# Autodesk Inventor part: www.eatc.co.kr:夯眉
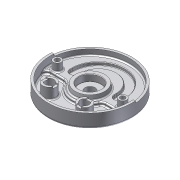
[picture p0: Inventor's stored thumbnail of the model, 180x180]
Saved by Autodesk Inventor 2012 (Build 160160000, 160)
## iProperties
Created: 2015-05
Document SubType Name: Modeling
Density: 2.71 g/cm^3
Material: 알루미늄-6061
Mass: 1082.54 g
Surface Area: 1038.66 cm^2
Volume: 399.463 cm^3
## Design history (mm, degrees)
sketch "스케치1"
  geometry: L1 (-59, -19)-(-59, 19); L2 (59, 19)-(59, -19); L3 (-41, 19)-(-41, -19); L4 (41, -19)-(41, 19); L5 (59, 5)-(41, 5); L6 (-41, 5)-(-59, 5); C1 r 90 at (0, 0); C2 r 95 at (0, 0); A1 r 59 centre (0, 19) between (59, 19) and (-59, 19); A2 r 59 centre (0, -19) between (-59, -19) and (59, -19); A3 r 41 centre (0, -19) between (-41, -19) and (41, -19); A4 r 41 centre (0, 19) between (41, 19) and (-41, 19); 2 further points
  constraints: 12 end point, 8 point on circle, 6 centre point, 5 point on line, 4 tangent, 2 parallel, 1 coincident, 1 collinear, 1 horizontal alignment, 1 midpoint, 1 perpendicular, 1 vertical, 1 vertical alignment, 3 other
  dimensions: "d2" = 180 diameter of C1; "d3" = 156 dimension on A2 A1; "d4" = 118 distance between parallel lines of L2 L1; "d5" = 18 distance between parallel lines of L2 L4; "d8" = 190 diameter of C2; "d117" = 5 distance from line of L5 point (0, 0)
extrude "돌출1" new body sketch "스케치1" distance "d6" = 14; taper "d7" = 0 deg
extrude "돌출2" join sketch "스케치1" distance "d9" = 13; taper "d10" = 0 deg
extrude "돌출3" cut sketch "스케치1" distance "d11" = 7; taper "d12" = 0 deg
sketch "스케치2"
  geometry: C1 r 11.5 at (0, 0); 1 further point
  constraints: 1 centre point, 1 coincident
  dimensions: "d13" = 23 diameter of C1
extrude "돌출4" cut sketch "스케치2" stored distance "d14" = 7; taper "d15" = 0 deg
fillet "모깎기1"
fillet "모깎기2"
sketch "스케치3"
  geometry: L1 (-89.658, 7.844)-(-94.638, 8.28); L2 (89.658, 7.844)-(94.638, 8.28); L3 (0, 0)-(0, -90); A1 r 95 centre (0, 0) between (-94.638, 8.28) and (94.638, 8.28) reference; A2 r 90 centre (0, 0) between (-89.658, 7.844) and (89.658, 7.844) reference; 1 further point
  constraints: 6 end point, 5 point on circle, 1 point on line, 1 vertical, 1 other
  dimensions: "d16" = 190 deg dimension on L2 L1
extrude "돌출5" join sketch "스케치3" distance "d17" = 5; taper "d18" = 0 deg
hole "구멍1" diameter "d21" = 50; stored, may be unused: countersink angle "d25" = 90 deg, drill point angle "d27" = 0 deg; dims "d19" = 10, "d20" = 10, "d22" = 6, "d23" = 4, "d24" = 2, "d26" = 5
fillet "모깎기3" dims "d28" = 0.3
fillet "모깎기5" dims "d42" = 5
sketch "스케치4"
  geometry: C1 r 35 at (0, 0); C2 r 25 at (0, 0); 1 further point
  constraints: 2 centre point, 1 coincident
  dimensions: "d32" = 70 diameter of C1 (derived); "d36" = 10 radial gap between concentric circles of C1 C2
extrude "돌출6" join sketch "스케치4" distance "d33" = 10; taper "d34" = 0 deg
feature "면 기울기2" dims angle "d37" = 10 deg
chamfer "모따기1" distance "d39" = 1; stored, may be unused: second distance "d40" = 2, angle "d41" = 45 deg
sketch "스케치5"
  geometry: L1 (-40.249, -12)-(-89.196, -12); L2 (40.249, -12)-(89.196, -12); A1 r 90 centre (0, 0) between (-89.196, -12) and (89.196, -12) reference; A2 r 42 centre (0, 0) between (-40.249, -12) and (40.249, -12); 1 further point
  constraints: 4 end point, 4 point on circle, 1 centre point, 1 collinear, 1 horizontal, 1 point on line
  dimensions: "d43" = 48 radial gap between concentric circles of A1 A2; "d44" = 12 distance from line of point (0, 0) L1
extrude "돌출7" cut sketch "스케치5" stored distance "d45" = 10; taper "d46" = 0 deg
fillet "모깎기8" dims "d47" = 10
chamfer "모따기2" distance "d49" = 1; stored, may be unused: second distance "d50" = 2, angle "d51" = 45 deg
sketch "스케치7"
  geometry: L1 (36.062, 36.062)-(50.912, 50.912); L2 (-36.062, 36.062)-(-50.912, 50.912); A1 r 72 centre (0, 0) between (50.912, 50.912) and (-50.912, 50.912); A2 r 51 centre (0, 0) between (36.062, 36.062) and (-36.062, 36.062); 1 further point
  constraints: 8 point on circle, 4 end point, 2 centre point, 2 point on line, 1 coincident, 1 horizontal alignment
  dimensions: "d54" = 72 radius of A1; "d55" = 21 radial gap between concentric circles of A1 A2; "d56" = 90 deg angle of L2 L1
extrude "돌출8" join sketch "스케치7" distance "d57" = 5; taper "d58" = 0 deg
fillet "모깎기10" dims "d59" = 5
fillet "모깎기11" dims "d60" = 5
fillet "모깎기12" dims "d61" = 3
sketch "스케치8"
  geometry: C1 r 9 at (74, 0); C2 r 9 at (-74, 0); A1 r 74 centre (0, 0) between (74, 0) and (-74, 0); 1 further point
  constraints: 3 centre point, 2 horizontal alignment, 2 point on circle, 1 coincident, 1 equal radius
  dimensions: "d64" = 18 diameter of C1; "d65" = 148 diameter of A1
extrude "돌출9" join sketch "스케치8" stored distance "d66" = 5; taper "d67" = 0 deg
sketch "스케치11"
  geometry: C1 r 15 at (40, -52); C2 r 15 at (-40, -52); 1 further point
  constraints: 2 centre point, 1 equal radius, 1 horizontal alignment
  dimensions: "d83" = 52 vertical distance of point (0, 0) C1.centre; "d84" = 80 distance of C2.centre C1.centre; "d85" = 40 horizontal distance of point (0, 0) C1.centre (= 0.5 x d84); "d86" = 30 diameter of C1
extrude "돌출10" join sketch "스케치11" stored distance "d87" = 5; taper "d88" = 0 deg
node "구멍3"
node "구멍5"
hole "구멍6" diameter "d93" = 20; stored, may be unused: countersink angle "d97" = 90 deg, drill point angle "d99" = 118 deg; dims "d91" = 10, "d92" = 10, "d94" = 6, "d95" = 4, "d96" = 2, "d98" = 8
hole "구멍7" diameter "d102" = 20; stored, may be unused: countersink angle "d106" = 90 deg, drill point angle "d108" = 118 deg; dims "d100" = 10, "d101" = 10, "d103" = 6, "d104" = 4, "d105" = 2, "d107" = 8
sketch "스케치13"
  geometry: L1 (6, -13.748)-(6, -8); L2 (6, 8)-(6, 13.748); L3 (-6, -13.748)-(-6, -8); L4 (-6, 8)-(-6, 13.748); L5 (-66.252, -6)-(-72, -6); L6 (-88, -6)-(-93.748, -6); L7 (-66.252, 6)-(-72, 6); L8 (-88, 6)-(-93.748, 6); A1 r 15 centre (0, 0) between (6, -13.748) and (6, 13.748) reference; A2 r 10 centre (0, 0) between (6, -8) and (6, 8) reference; A3 r 15 centre (-80, 0) between (-66.252, -6) and (-93.748, -6) reference; A4 r 10 centre (-80, 0) between (-72, -6) and (-88, -6) reference; 1 further point
  constraints: 16 end point, 16 point on circle, 4 equal length, 3 collinear, 2 point on line, 1 perpendicular, 1 vertical
  dimensions: "d109" = 12 distance between parallel lines of L3 L1; "d110" = 6 distance from line of A1.centre L1 (= 0.5 x d109); "d111" = 12 distance between parallel lines of L7 L5; "d112" = 6 distance from line of A3.centre L5 (= 0.5 x d111)
extrude "돌출12" cut sketch "스케치13" distance "d113" = 3; taper "d114" = 0 deg
fillet "모깎기13" dims "d115" = 3
fillet "모깎기14" dims "d116" = 1
sketch "스케치14"
  geometry: C1 r 25 at (0, 0); C2 r 11.5 at (0, 0) reference; 1 further point
  constraints: 1 centre point, 1 coincident
  dimensions: "d120" = 50 diameter of C1
extrude "돌출13" join sketch "스케치14" distance "d121" = 12; taper "d122" = 0 deg
feature "면 기울기3" dims angle "d123" = 15 deg
chamfer "모따기3" distance "d125" = 1; stored, may be unused: second distance "d126" = 2, angle "d127" = 45 deg
fillet "모깎기15" dims "d124" = 3
sketch "스케치6"
  geometry: C1 r 68 at (0, 0); 1 further point
  constraints: 1 centre point, 1 other
  dimensions: "d119" = 136 diameter of C1
feature "엠보싱1" sketch "스케치6" dims "d62" = 0.5, "d63" = 0
node "솔리드1"
fillet "모깎기4" dims "d30" = 3
sketch "스케치9"
  geometry: 1 further point
hole "구멍2" sketch "스케치9" diameter "d68" = 11; stored, may be unused: countersink angle "d72" = 90 deg, drill point angle "d74" = 0 deg; dims "d69" = 6, "d70" = 18, "d71" = 11, "d73" = 8
sketch "스케치10"
  geometry: 1 further point
hole "구멍4" sketch "스케치10" diameter "d75" = 11; stored, may be unused: countersink angle "d79" = 90 deg, drill point angle "d81" = 0 deg; dims "d76" = 6, "d77" = 18, "d78" = 11, "d80" = 8
